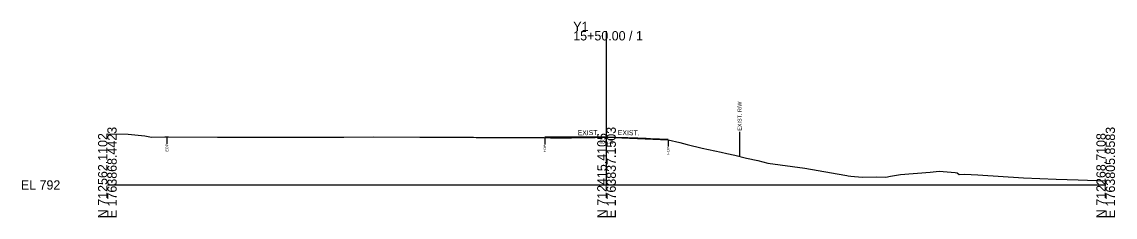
# Model space of a CAD drawing. Extents: x -26 to 1303, y -10 to 9524.
# Drawn here: x -25.7 to 302.8, y 5490.3 to 5549.1 of the extents above; entities that cross this region are included whole.
import ezdxf

# ---------------------------------------------------------------- set-up
doc = ezdxf.new("R2010")
doc.units = 0
for name, color, linetype in [('Default', 7, 'Continuous'), ('Exist Cross Section Cell', 7, 'Continuous'), ('Exist XS Center Line Elevation Label', 7, 'Continuous'), ('Exist XS Ground Line', 7, 'Continuous'), ('Old_Level_10', 7, 'Continuous'), ('Prop CMT Pvmt Course 1', 7, 'Continuous'), ('Prop CMT Pvmt Surface Overlay', 7, 'Continuous'), ('Prop XS SE Text', 7, 'Continuous')]:
    doc.layers.add(name, color=color, linetype=linetype)

msp = doc.modelspace()

# ---------------------------------------------------------------- linework, layer by layer
at = {"layer": 'Exist Cross Section Cell'}
for p, q in [((150, 5500), (150, 5546.3)), ((0, 5500), (150, 5500)), ((150, 5500), (300, 5500))]:
    msp.add_line(p, q, dxfattribs=at)
at = {"layer": 'Exist XS Ground Line'}
msp.add_lwpolyline([(0, 5515.43), (6.28, 5515.29), (11.3, 5514.82), (13.25, 5514.37), (17.29, 5514.46), (18.35, 5514.48), (33.11, 5514.42), (48.12, 5514.4), (50.17, 5514.4), (54.08, 5514.36), (56.39, 5514.36), (62.08, 5514.38), (71.11, 5514.4), (79.97, 5514.44), (93.85, 5514.41), (99.35, 5514.41), (105.69, 5514.35), (106.38, 5514.35), (107.91, 5514.35), (108.24, 5514.35), (110.02, 5514.34), (110.8, 5514.32), (112.13, 5514.3), (113.35, 5514.3), (114.23, 5514.29), (115.91, 5514.28), (116.34, 5514.28), (118.49, 5514.28), (121.02, 5514.28), (121.74, 5514.27), (123.58, 5514.27), (124.77, 5514.26), (126.14, 5514.26), (126.88, 5514.27), (128.82, 5514.3), (129.43, 5514.29), (129.73, 5514.28), (130.16, 5514.25), (131.25, 5514.26), (133.2, 5514.22), (133.8, 5514.21), (135.3, 5514.2), (136.36, 5514.21), (137.99, 5514.21), (138.92, 5514.22), (139.52, 5514.22), (141.62, 5514.24), (142.33, 5514.25), (144.03, 5514.29), (145.84, 5514.32), (146.59, 5514.33), (147.94, 5514.34), (149.14, 5514.38), (150.21, 5514.39), (150.72, 5514.39), (151.7, 5514.38), (152.16, 5514.36), (154.32, 5514.32), (156.37, 5514.24), (156.81, 5514.22), (158.48, 5514.18), (159.37, 5514.16), (160.59, 5514.12), (161.92, 5514.07), (162.69, 5514.02), (164.48, 5513.87), (165.07, 5513.83), (166.09, 5513.79), (167.03, 5513.73), (168.53, 5513.62), (171.98, 5512.77), (174.2, 5512.17), (178.77, 5511.06), (184.42, 5509.85), (186.16, 5509.44), (188.57, 5508.99), (192.09, 5508.06), (195.46, 5507.36), (198.44, 5506.54), (209.55, 5505.02), (221.59, 5502.96), (222.19, 5502.85), (222.63, 5502.78), (223.43, 5502.63), (226.8, 5502.34), (231.04, 5502.4), (233.93, 5502.38), (235.35, 5502.62), (238.3, 5503.17), (247.21, 5503.86), (249.97, 5504.12), (254.79, 5503.73), (255.4, 5503.66), (255.95, 5503.15), (257.58, 5503.2), (261.62, 5503.02), (275.26, 5502.18), (285.13, 5501.74), (291.75, 5501.57), (300, 5501.29)], dxfattribs=at)
at = {"layer": 'Old_Level_10'}
for p, q in [((17.91, 5514.47), (17.91, 5512.42)), ((131.46, 5514.26), (131.46, 5512.21)), ((168.53, 5513.62), (168.53, 5511.57)), ((190, 5516.02), (190, 5508.61))]:
    msp.add_line(p, q, dxfattribs=at)
at = {"layer": 'Prop CMT Pvmt Course 1'}
for q in [(131.46, 5514.26), (168.53, 5513.62)]:
    msp.add_line((150, 5514.39), q, dxfattribs=at)
at = {"layer": 'Prop CMT Pvmt Surface Overlay'}
for q in [(131.46, 5514.38), (168.54, 5513.74)]:
    msp.add_line((150, 5514.51), q, dxfattribs=at)

# ---------------------------------------------------------------- texts
at = {"layer": 'Default'}
msp.add_text('-', height=0.0001, dxfattribs=at).set_placement((0, 5500))
at = {"layer": 'Exist Cross Section Cell'}
for s, p in [('Y1', (140, 5546.3)), ('15+50.00 / 1', (140, 5543.5)), ('EL 792', (-26, 5498.6))]:
    msp.add_text(s, height=2.8, dxfattribs=at).set_placement(p)
for s, p in [('E 1763868.4423', (2.8, 5490)), ('E 1763837.1503', (152.8, 5490)), ('E 1763805.8583', (302.8, 5490)), ('N 712562.1102', (0, 5490)), ('N 712415.4105', (150, 5490)), ('N 712268.7108', (300, 5490))]:
    msp.add_text(s, height=2.8, rotation=90, dxfattribs=at).set_placement(p)
at = {"layer": 'Exist XS Center Line Elevation Label'}
msp.add_text('806.39', height=1, dxfattribs=at).set_placement((147.87, 5512.39))
at = {"layer": 'Old_Level_10'}
for s, height, p in [('EXIST. R/W', 1.181, (190.59, 5516.32)), ('EOP', 0.787, (18.3, 5510.02)), ('EOP', 0.787, (131.85, 5509.81)), ('EOP', 0.787, (168.92, 5509.17))]:
    msp.add_text(s, height=height, rotation=90, dxfattribs=at).set_placement(p)
at = {"layer": 'Prop XS SE Text'}
for rotation, p in [(1.1458, (141.33, 5514.93)), (358.8542, (153.37, 5515.04))]:
    msp.add_text('EXIST.', height=1.5, rotation=rotation, dxfattribs=at).set_placement(p)

doc.saveas('drawing.dxf')
